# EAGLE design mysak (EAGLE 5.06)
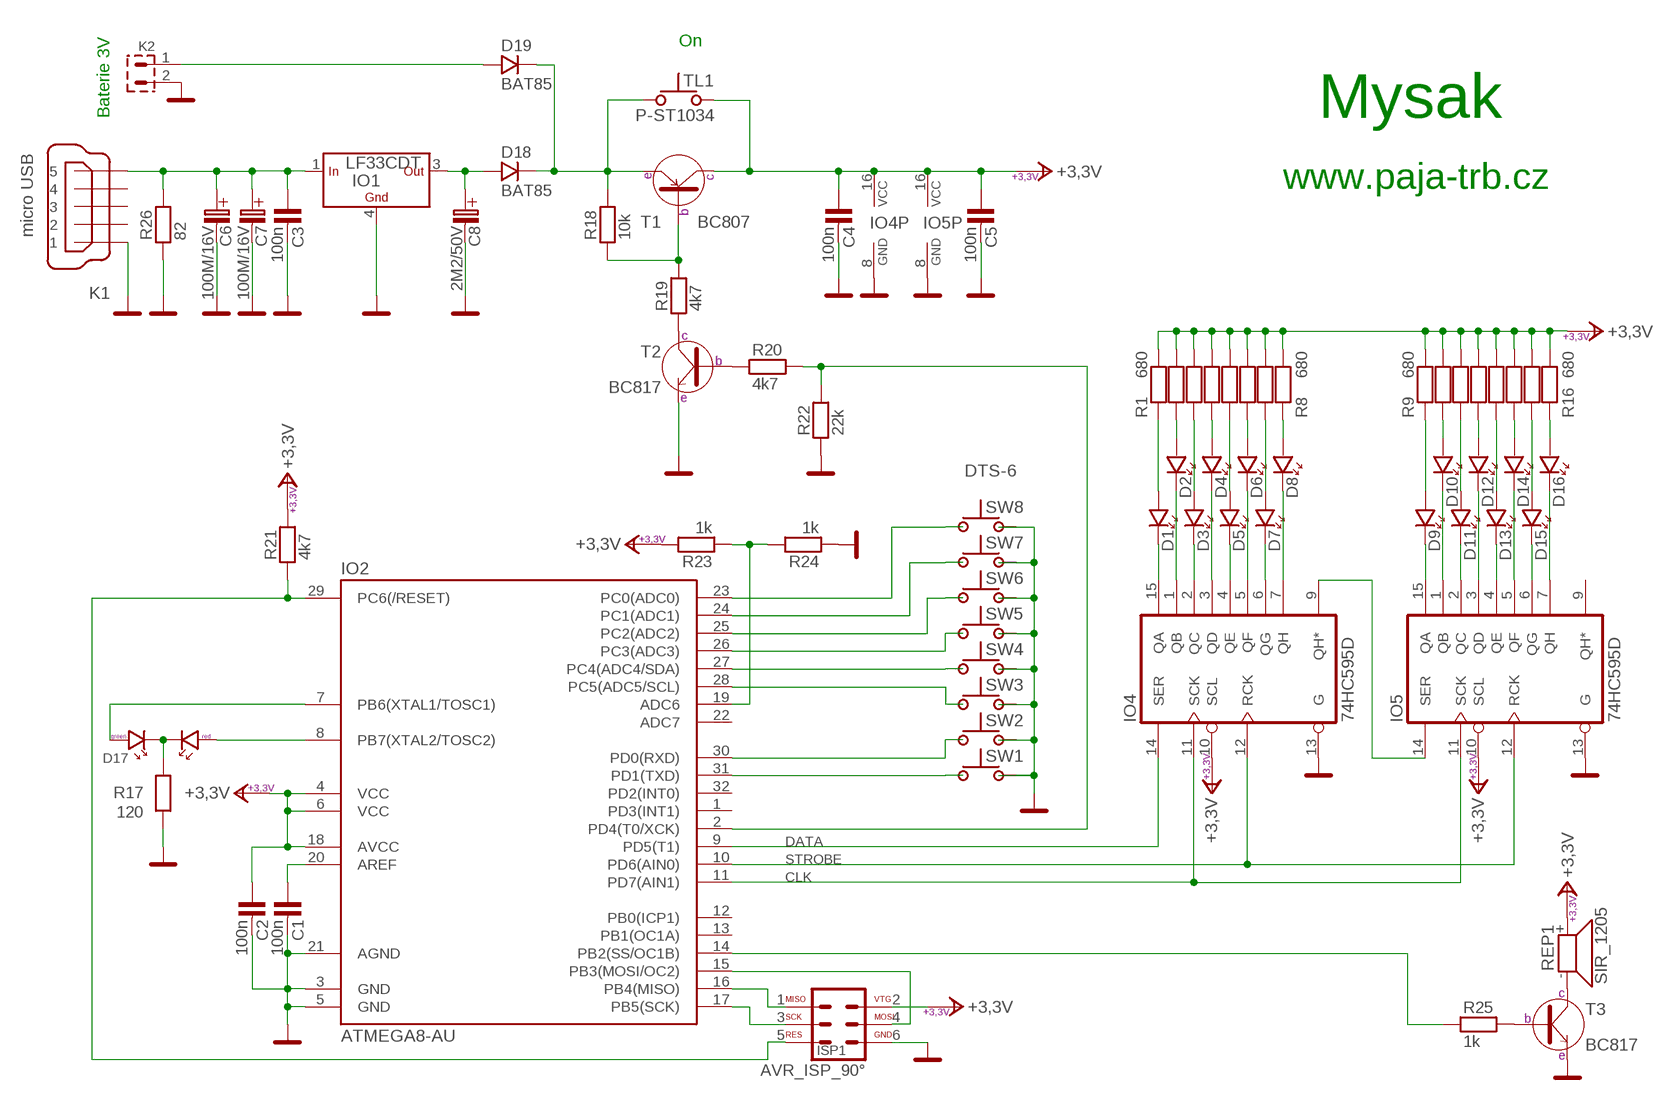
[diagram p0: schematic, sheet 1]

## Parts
C1  100n  C-KER_0805  [0805]
C2  100n  C-KER_0805  [0805]
C3  100n  C-KER_1206  [1206]
C4  100n  C-KER_1206  [1206]
C5  100n  C-KER_1206  [1206]
C6  100M/16V  100M/16V_SMD  [C_EL-SMD_D]
C7  100M/16V  100M/16V_SMD  [C_EL-SMD_D]
C8  2M2/50V  [C_EL_2]
D1  LED_3  [LED_3]
D2  LED_3  [LED_3]
D3  LED_3  [LED_3]
D4  LED_3  [LED_3]
D5  LED_3  [LED_3]
D6  LED_3  [LED_3]
D7  LED_3  [LED_3]
D8  LED_3  [LED_3]
D9  LED_3  [LED_3]
D10  LED_3  [LED_3]
D11  LED_3  [LED_3]
D12  LED_3  [LED_3]
D13  LED_3  [LED_3]
D14  LED_3  [LED_3]
D15  LED_3  [LED_3]
D16  LED_3  [LED_3]
D17  LED_DUO_5  [LED_5-DUO]
D18  BAT85  D_7,5  [DO35]
D19  BAT85  D_7,5  [DO35]
IO1  LF33CDT  LF_CDT  [DPAK]
IO2  ATMEGA8-AU  [TQFP32-08]
IO4  74HC595D  [SO16]
IO5  74HC595D  [SO16]
ISP1  AVR_ISP_90°  [MLW06A]
K1  micro USB  MINI-USB-UX60A-MB-5ST  [UX60A-MB-5ST]
K2  PSH02-02W  [PSH02-02W]
R1  680  R_0805  [0805]
R2  680  R_0805  [0805]
R3  680  R_0805  [0805]
R4  680  R_0805  [0805]
R5  680  R_0805  [0805]
R6  680  R_0805  [0805]
R7  680  R_0805  [0805]
R8  680  R_0805  [0805]
R9  680  R_0805  [0805]
R10  680  R_0805  [0805]
R11  680  R_0805  [0805]
R12  680  R_0805  [0805]
R13  680  R_0805  [0805]
R14  680  R_0805  [0805]
R15  680  R_0805  [0805]
R16  680  R_0805  [0805]
R17  120  R_0805  [0805]
R18  10k  R_1206  [1206]
R19  4k7  R_1206  [1206]
R20  4k7  R_1206  [1206]
R21  4k7  R_7,5  [R-7,5]
R22  22k  R_1206  [1206]
R23  1k  R_0805  [0805]
R24  1k  R_0805  [0805]
R25  1k  R_1206  [1206]
R26  82  R__2W  [R-_2W]
REP1  SIR_1205  [LD-BZEG-1205]
SW1  DTS-6  [DTS-6]
SW2  DTS-6  [DTS-6]
SW3  DTS-6  [DTS-6]
SW4  DTS-6  [DTS-6]
SW5  DTS-6  [DTS-6]
SW6  DTS-6  [DTS-6]
SW7  DTS-6  [DTS-6]
SW8  DTS-6  [DTS-6]
T1  BC807  [SOT-23]
T2  BC817  [SOT-23]
T3  BC817  [SOT-23]
TL1  P-ST1034  [P-ST1034]

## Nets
+3,3V: C2.1 C4.1 C5.1 IO2.4(VCC) IO2.6(VCC) IO2.18(AVCC) IO4.10(SCL) IO4.16(VCC) IO5.10(SCL) IO5.16(VCC) ISP1.2 R1.2 R2.2 R3.2 R4.2 R5.2 R6.2 R7.2 R8.2 R9.2 R10.2 R11.2 R12.2 R13.2 R14.2 R15.2 R16.2 R21.2 R23.2 REP1.+ T1.3(C) TL1.S
CLK: IO2.11(PD7(AIN1)) IO4.11(SCK) IO5.11(SCK)
D2: D1.A R1.1
D3: D4.K IO4.3(QD)
DATA: IO2.9(PD5(T1)) IO4.14(SER)
DD: D17.K R17.2
GND: C1.2 C2.2 C3.2 C4.2 C5.2 C6.-(C_EL-) C7.-(C_EL-) C8.C-(C_EL-) IO1.4(GND) IO2.3(GND) IO2.5(GND) IO2.21(AGND) IO4.8(GND) IO4.13(G) IO5.8(GND) IO5.13(G) ISP1.6 K1.1 K2.2 R17.1 R22.1 R24.1 R26.1 SW1.3 SW1.4(2A) SW2.3 SW2.4(2A) SW3.3 SW3.4(2A) SW4.3 SW4.4(2A) SW5.3 SW5.4(2A) SW6.3 SW6.4(2A) SW7.3 SW7.4(2A) SW8.3 SW8.4(2A) T2.2(E) T3.2(E)
N$1: D17.A1 IO2.8(PB7(XTAL2/TOSC2))
N$2: IO4.9(QH*) IO5.14(SER)
N$3: C1.1 IO2.20(AREF)
N$4: IO2.23(PC0(ADC0)) SW8.1 SW8.2(1A)
N$5: IO2.29(PC6(/RESET)) ISP1.5 R21.1
N$6: IO2.16(PB4(MISO)) ISP1.1
N$7: IO2.17(PB5(SCK)) ISP1.3
N$8: IO2.15(PB3(MOSI/OC2)) ISP1.4
N$9: IO2.24(PC1(ADC1)) SW7.1 SW7.2(1A)
N$10: IO2.25(PC2(ADC2)) SW6.1 SW6.2(1A)
N$11: IO2.26(PC3(ADC3)) SW5.1 SW5.2(1A)
N$12: IO2.27(PC4(ADC4/SDA)) SW4.1 SW4.2(1A)
N$13: IO2.28(PC5(ADC5/SCL)) SW3.1 SW3.2(1A)
N$14: IO2.30(PD0(RXD)) SW2.1 SW2.2(1A)
N$15: IO2.31(PD1(TXD)) SW1.1 SW1.2(1A)
N$16: IO2.19(ADC6) R23.1 R24.2
N$17: C8.C+(C_EL+) D18.A IO1.3(OUT)
N$18: D17.A2 IO2.7(PB6(XTAL1/TOSC1))
N$20: R19.1 T2.3(C)
N$21: R20.1 T2.1(B)
N$22: D18.K D19.K R18.2 T1.2(E) TL1.1
N$23: R18.1 R19.2 T1.1(B)
N$24: IO2.2(PD4(T0/XCK)) R20.2 R22.2
N$26: IO2.14(PB2(SS/OC1B)) R25.1
N$35: REP1.- T3.3(C)
N$36: D2.A R2.1
N$37: D4.A R4.1
N$39: D6.A R6.1
N$40: D8.A R8.1
N$41: D10.A R10.1
N$42: D12.A R12.1
N$43: D14.A R14.1
N$44: D16.A R16.1
N$46: D3.A R3.1
N$47: D5.A R5.1
N$48: D7.A R7.1
N$49: D8.K IO4.7(QH)
N$50: D6.K IO4.5(QF)
N$51: D7.K IO4.6(QG)
N$52: D5.K IO4.4(QE)
N$54: D3.K IO4.2(QC)
N$55: D2.K IO4.1(QB)
N$56: D1.K IO4.15(QA)
N$57: D9.A R9.1
N$58: D9.K IO5.15(QA)
N$59: D10.K IO5.1(QB)
N$60: D12.K IO5.3(QD)
N$61: D11.K IO5.2(QC)
N$62: D11.A R11.1
N$63: D13.A R13.1
N$64: D13.K IO5.4(QE)
N$65: D14.K IO5.5(QF)
N$66: D15.A R15.1
N$67: D15.K IO5.6(QG)
N$68: D16.K IO5.7(QH)
N$69: C3.1 C6.+(C_EL+) C7.+(C_EL+) IO1.1(IN) K1.5 R26.2
N$70: D19.A K2.1
N$71: R25.2 T3.1(B)
STROBE: IO2.10(PD6(AIN0)) IO4.12(RCK) IO5.12(RCK)
Unconnected: IO2.1(PD3(INT1)) IO2.12(PB0(ICP1)) IO2.13(PB1(OC1A)) IO2.22(ADC7) IO2.32(PD2(INT0)) IO5.9(QH*) K1.2 K1.3 K1.4

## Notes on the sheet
- On
- Baterie 3V | Mysak
- www.paja-trb.cz

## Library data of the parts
C1-C5 = #PaJa_32:C-KER: Kondenzator - keramicky
C6 C7 = #PaJa_C-el_2:100M/16V
C8 = #PaJa_C-el_2:2M2/50V
D1-D16 = #PaJa_32:LED: LED - jednobarevna
D17 = #PaJa_32:LED_DUO: LED dioda - dvoubarevna - 3 vyvody, spol. Katoda
D18 D19 = #PaJa_32:D: Dioda - univerzální
IO1 = #PaJa_32:LF_C: LF??C - stabilizatory low-drop Out= 1,5 / 1,8 / 2,5 / 3,3 / 4,7 / 5 / 6 / 8 / 5,5 / 9 / 12 V Avaiable in +- 1% (AB) , +- 2% (C)
IO2 = atmega8:ATMEGA8
IO4 IO5 = 74xx-eu:74*595: 8-bit SHIFT REGISTER, output latch
ISP1 = #PaJa_32:AVR_ISP: AVR ISP konektor (dle standardu)
K1 = con-hirose:MINI-USB-: Hirose MINI USB Connector UX60-MB-5S8: Through-hole / SMT Supplier: UX60-MB-5ST: Through-hole / SMT Supplier: UX60A-MB-5ST: Through-hole / SMT Supplier: Source: http://www.hirose.co.jp/cataloge_hp/e24000019.pdf
K2 = #PaJa_konektory:PSH02-02: Konektory se zamkem - vidlice - 2pin
R1-R26 = #PaJa_32:R: Rezistor
REP1 = #PaJa_32:SIR: Piezo-sirenka - 70dB - 3V az 16V
SW1-SW8 = #PaJa_prepinace:DTS?6: &micro;-tlacitko
T1 = #PaJa_32:BC807: SMD tranzistor - PNP - ekv. BC327
T2 T3 = #PaJa_32:BC817: SMD tranzistor - NPN - ekv. BC337
TL1 = #PaJa_prepinace:P-ST1034: &micro;-spinac - (10x10mm)

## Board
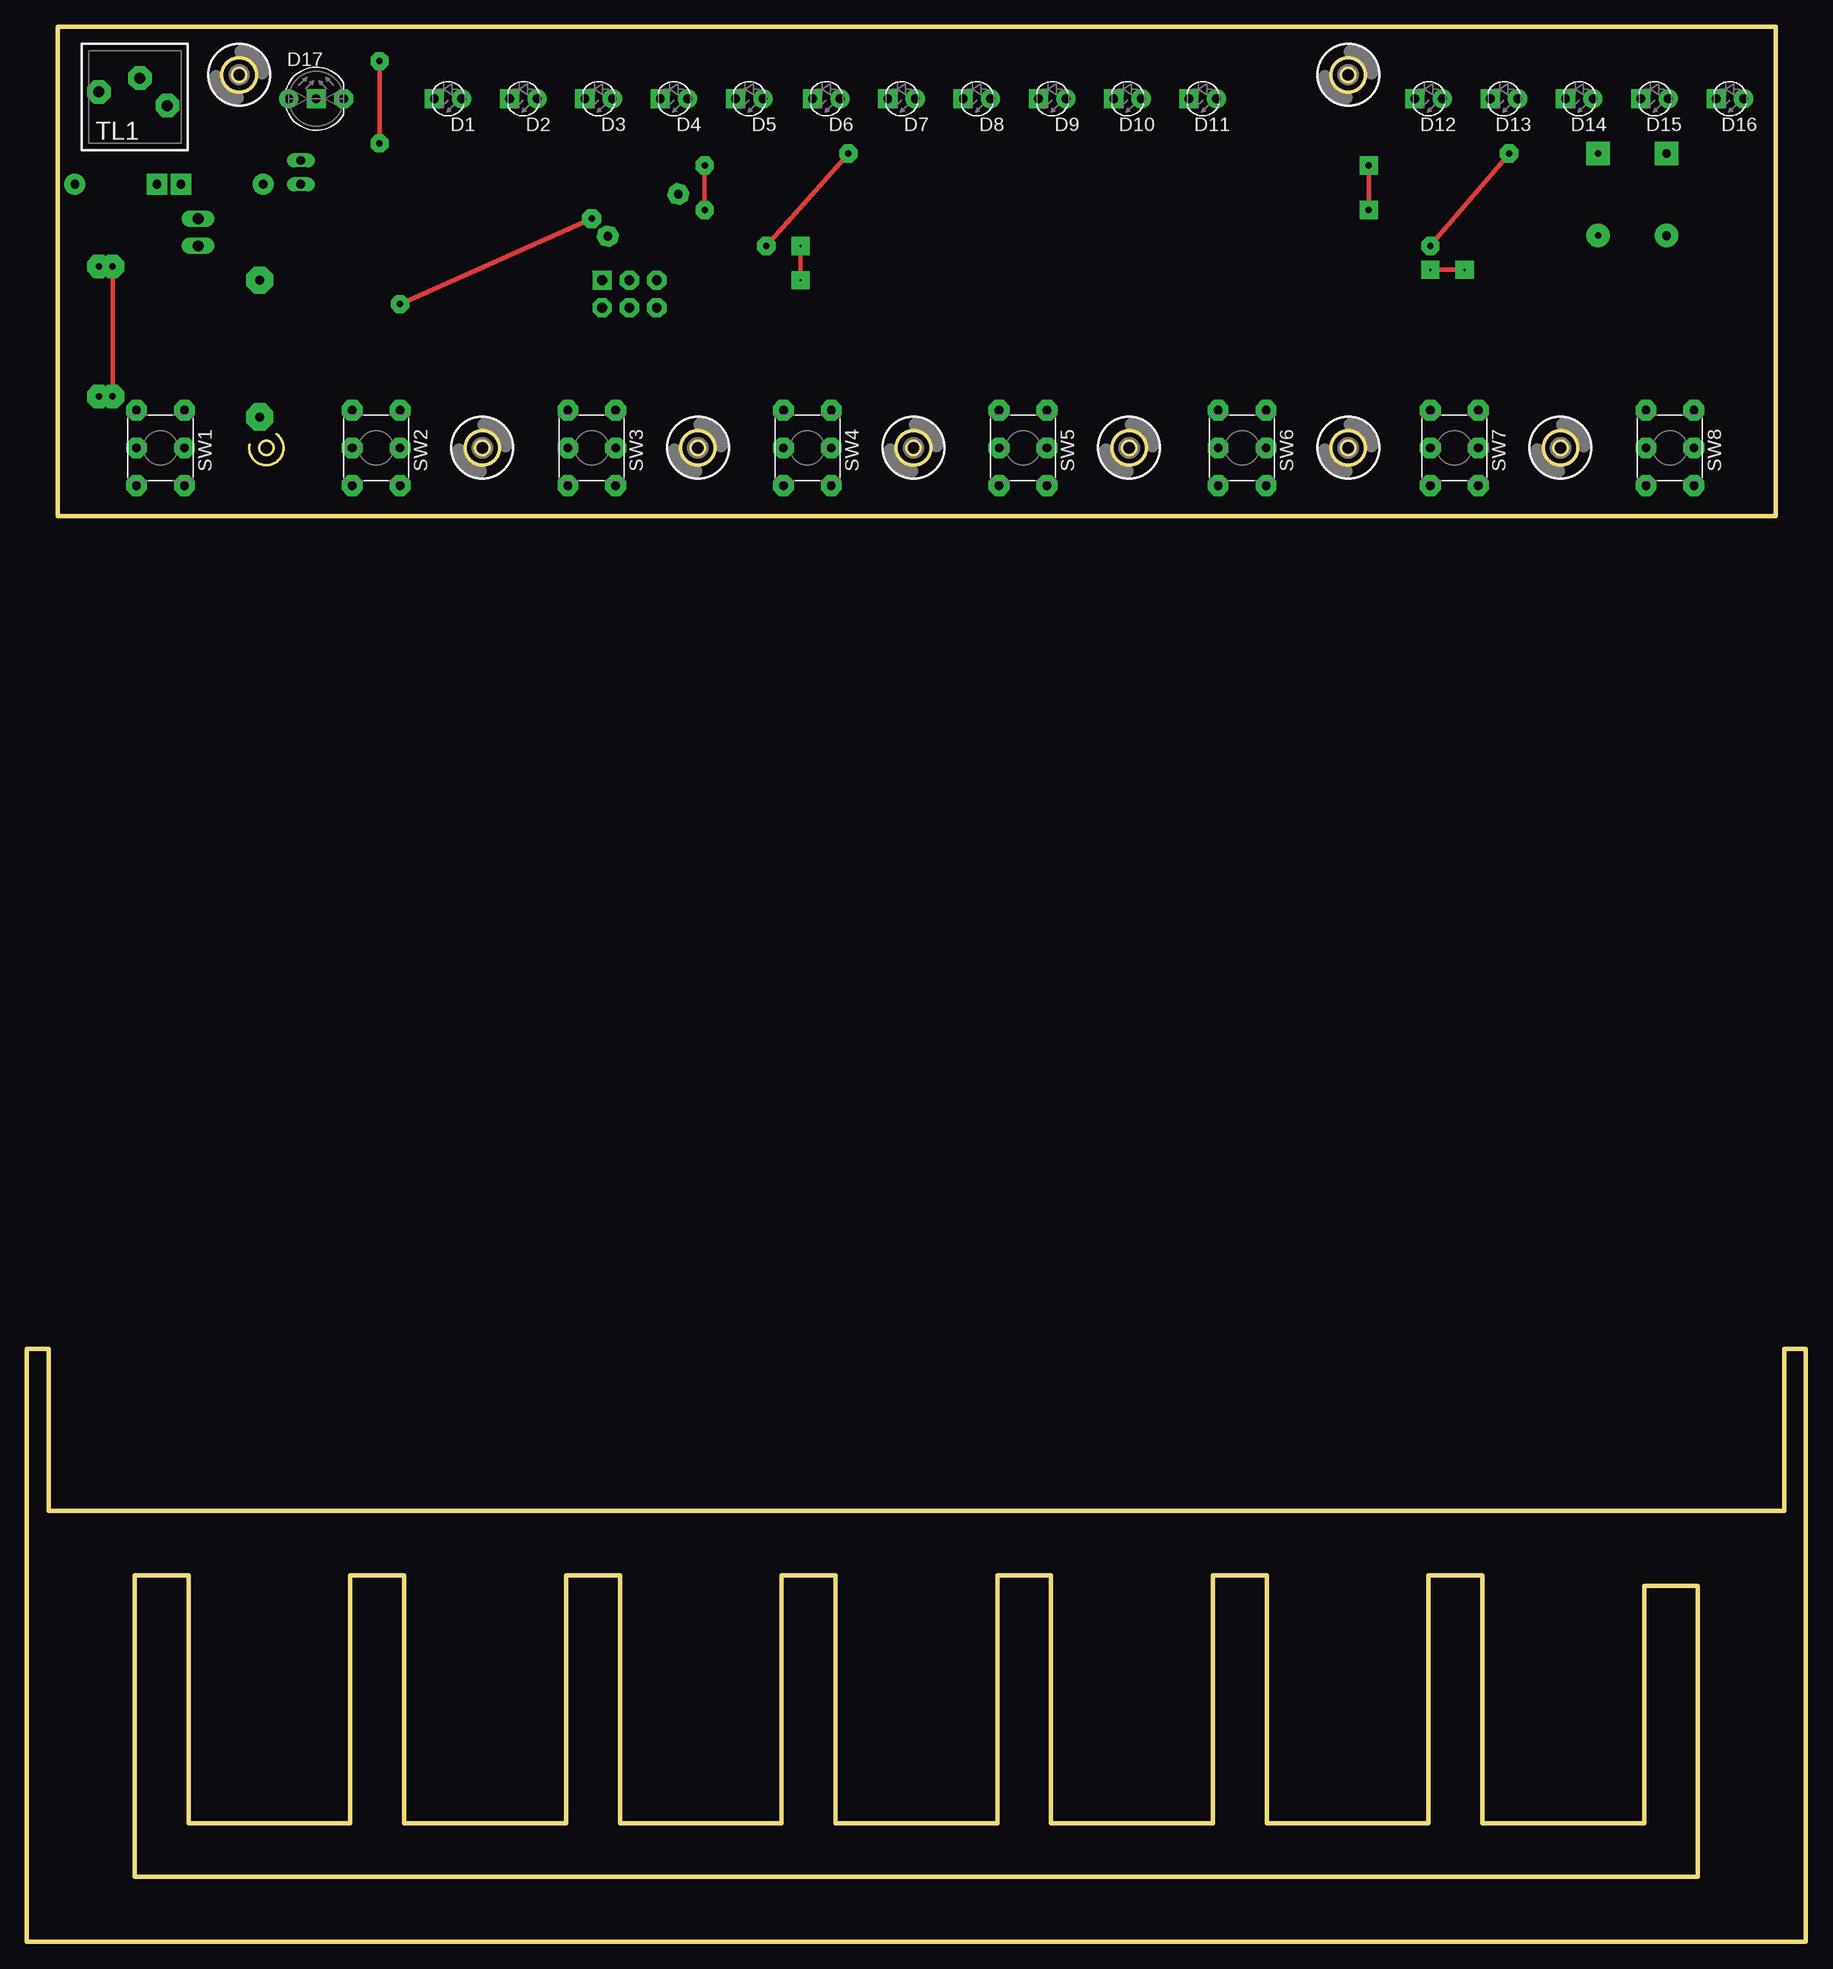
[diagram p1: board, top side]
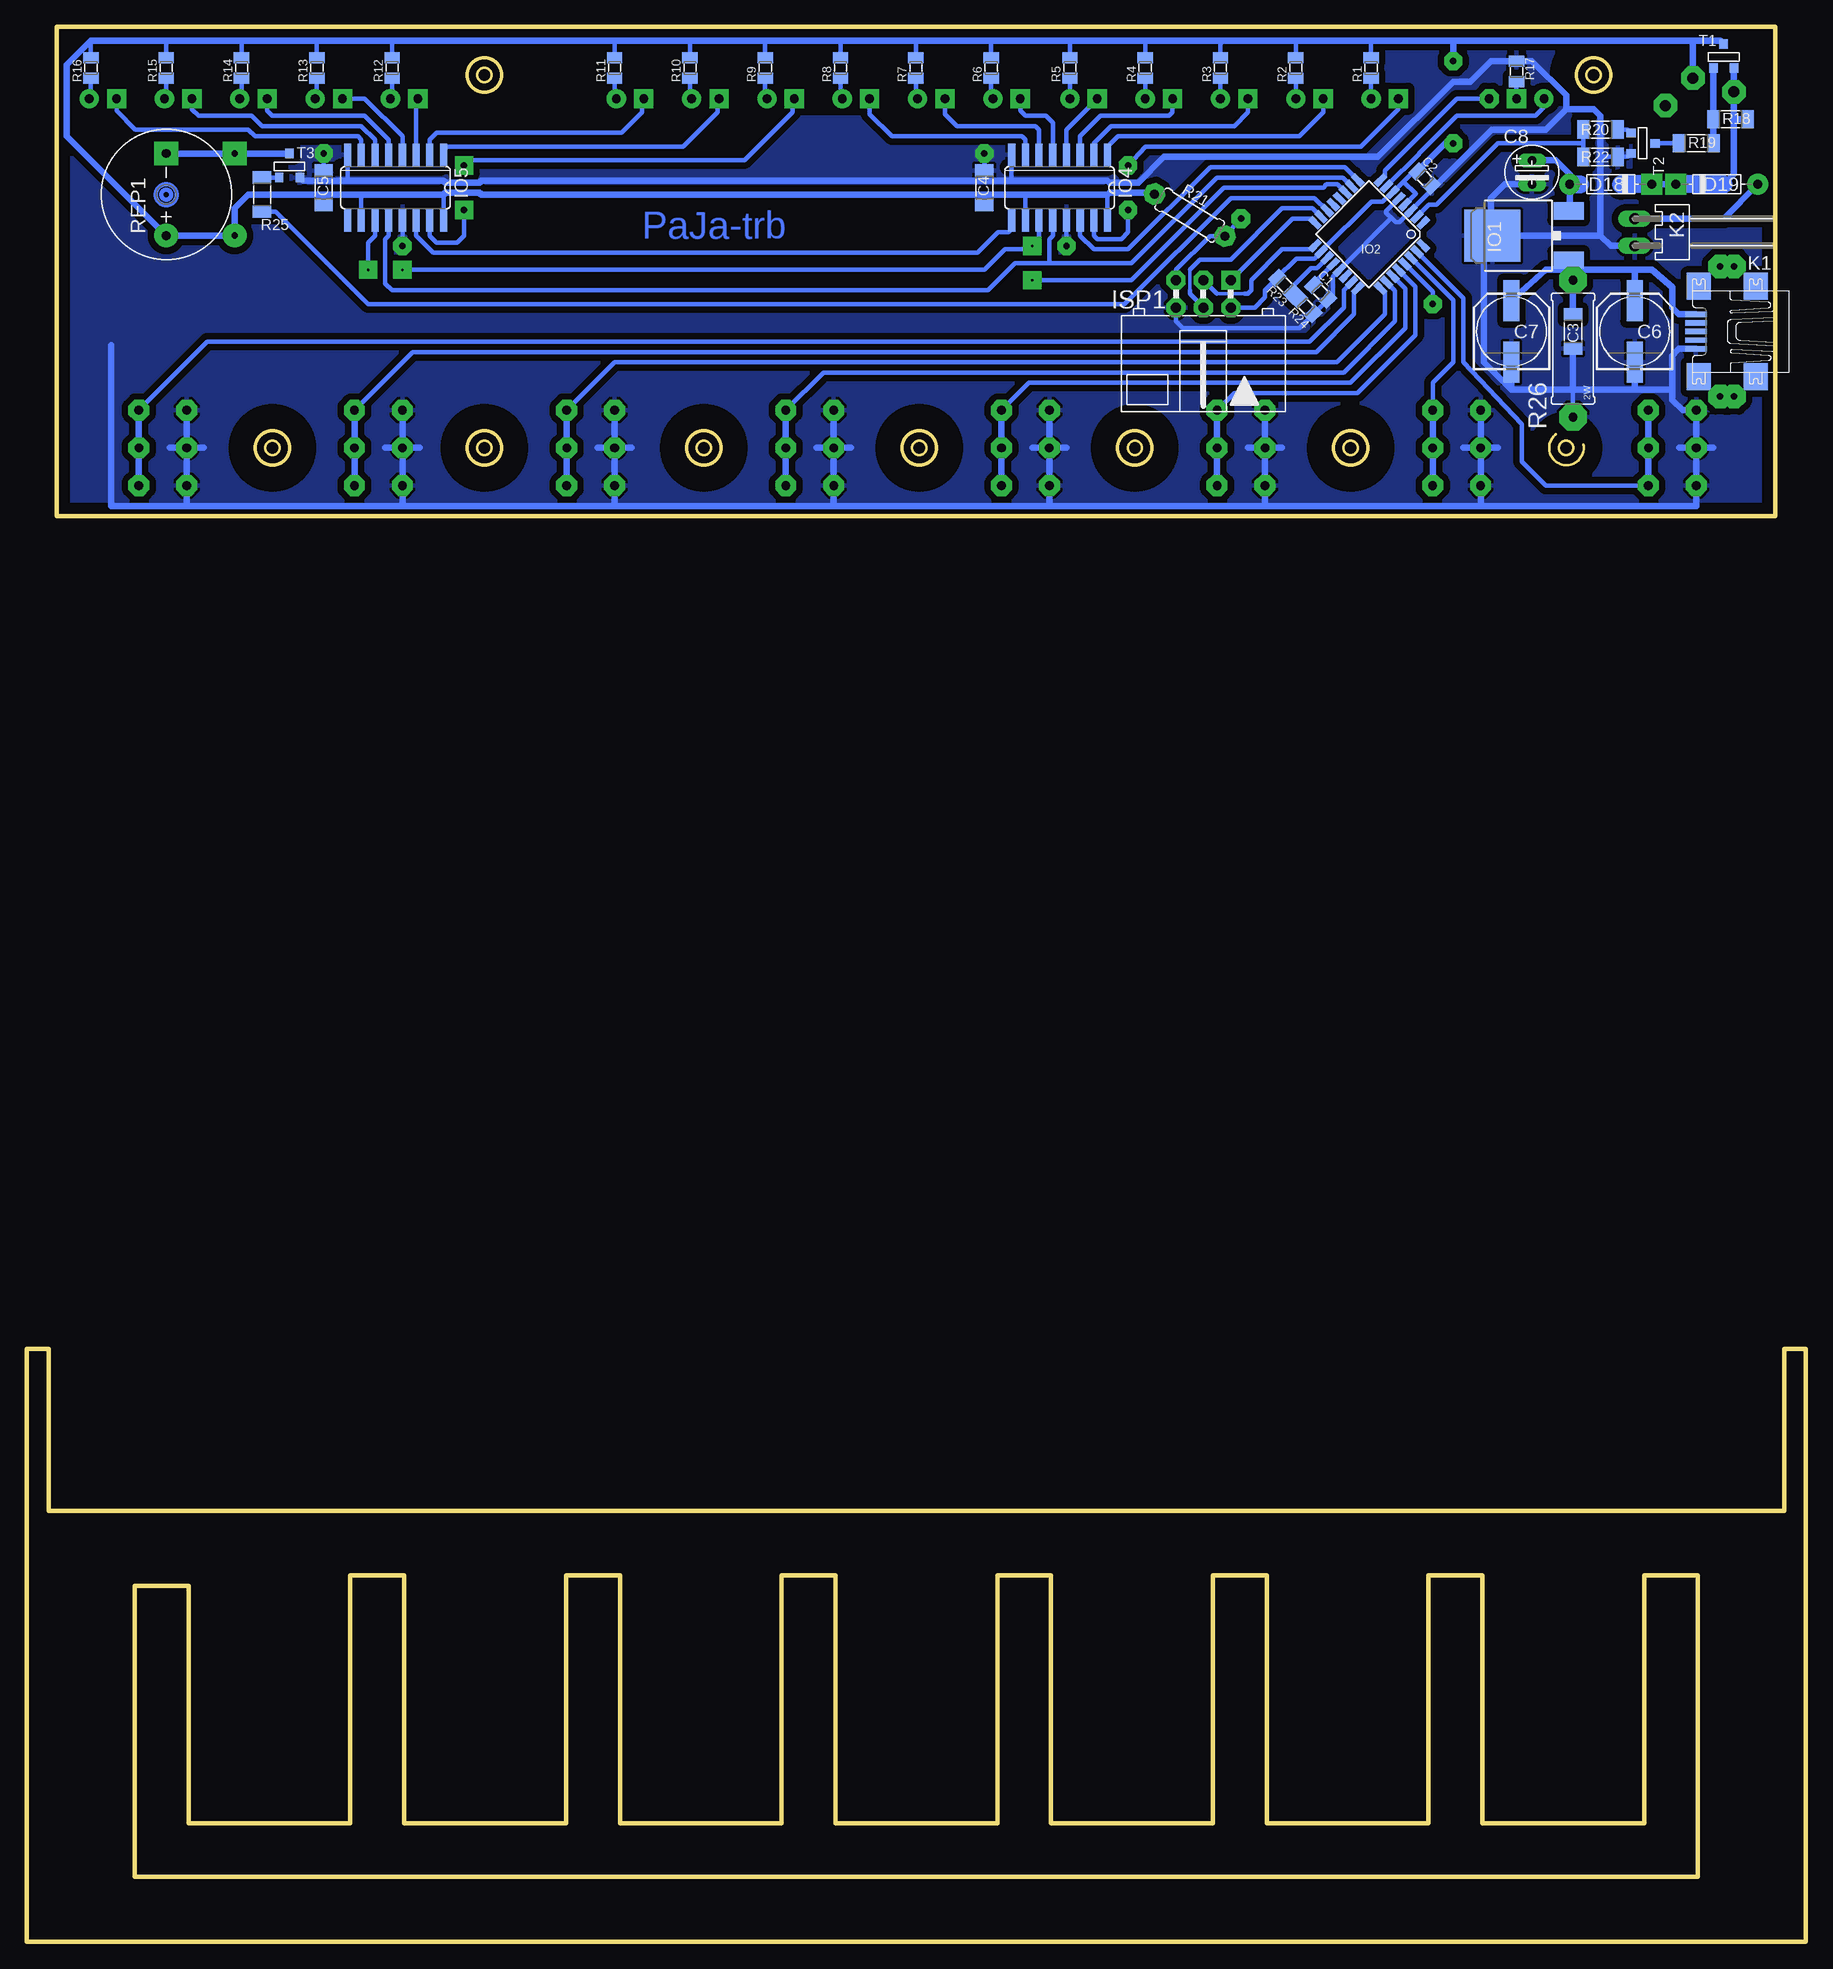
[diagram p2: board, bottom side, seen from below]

Size 165 x 177.6 mm. Coordinates in mm from the lower left corner, seen from the top.
Outline: 0,40 0,39.97
Outline: 0,39.97 0,0 165,0 165,39.97
Outline: 165,40 165,39.97
Outline: 0,39.97 0,54.97 2,54.97 2,39.97 163,39.97 163,54.97 165,54.97 165,39.97
Outline: 23.18,139.83 arc-244 20.64,138.88
Outline: 2.86,132.21 162.23,132.21 162.23,177.6 2.86,177.6 2.86,132.21
Outline: 10,34 15,34 15,11 30,11 30,34 35,34 35,11 50,11 50,34 55,34 55,11 70,11 70,34 75,34 75,11 90,11 90,34 95,34 95,11 110,11 110,34 115,34 115,11 130,11 130,34 135,34 135,11 150,11 150,33 155,33 155,6 10,6 10,34
Outline: circle at 22.23,138.56 radius 0.64
Copper layers (1*16): Top 0.035mm / dielectric 1.5mm / Bottom 0.035mm
Design rules "default": minimum track width 10mil, minimum drill 24mil, track to track 8mil, track to pad 8mil, pad to pad 8mil, via to via 8mil, smd to smd 8mil, copper to edge 40mil, drill to drill 8mil, minimum pad ring 10mil, minimum via ring 8mil, stop-mask expansion 4mil, vias tented up to drill 0mil, thermal gap 10mil
bRestrict: area 9.7,138.1 to 10.6,139; area 29.7,138.1 to 30.6,139; area 49.7,138.1 to 50.6,139; area 69.7,138.1 to 70.6,139; area 89.7,138.1 to 90.6,139; area 110,138.1 to 110.9,139; area 129.7,138.1 to 130.6,139; area 149.7,138.1 to 150.6,139; area 19.7,136 to 24.8,141.1; 8 lines

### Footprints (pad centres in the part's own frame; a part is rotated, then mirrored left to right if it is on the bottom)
0805 = smd 1.016 x 1.422: 1 -0.953,0; 2 0.953,0
1206 = smd 1.143 x 1.702: 1 -1.587,0; 2 1.587,0
C_EL-SMD_D = smd 3.81 x 1.473: + 2.857,0; - -2.857,0
C_EL_2 = drill 0.813 pad 1.27 long: C+ 0,0; C- 2.223,0
LED_3 = drill 0.813 pad 1.778 round: A -1.27,0 | drill 0.813 pad 1.778 square: K 1.27,0
LED_5-DUO = drill 0.813 pad 1.778 octagon: A1 2.54,0 | drill 0.813 pad 1.778 round: A2 -2.54,0 | drill 0.813 pad 1.778 square: K 0,0
DO35 = drill 0.813 pad 1.93 round: A -3.81,0 | drill 0.813 pad 1.93 square: K 3.81,0
DPAK = smd 1.6 x 2.8: 1 -2.28,-4.992; 3 2.28,-4.992 | smd 4.826 x 5.191: 4 0,2.096
TQFP32-08 = smd 1.27 x 0.559: 1 -4.293,2.8; 2 -4.293,2; 3 -4.293,1.2; 4 -4.293,0.4; 5 -4.293,-0.4; 6 -4.293,-1.2; 7 -4.293,-2; 8 -4.293,-2.8; 17 4.293,-2.8; 18 4.293,-2; 19 4.293,-1.2; 20 4.293,-0.4; 21 4.293,0.4; 22 4.293,1.2; 23 4.293,2; 24 4.293,2.8 | smd 0.559 x 1.27: 9 -2.8,-4.293; 10 -2,-4.293; 11 -1.2,-4.293; 12 -0.4,-4.293; 13 0.4,-4.293; 14 1.2,-4.293; 15 2,-4.293; 16 2.8,-4.293; 25 2.8,4.293; 26 2,4.293; 27 1.2,4.293; 28 0.4,4.293; 29 -0.4,4.293; 30 -1.2,4.293; 31 -2,4.293; 32 -2.8,4.293
SO16 = smd 0.66 x 2.032: 1 -4.445,-3.073; 2 -3.175,-3.073; 3 -1.905,-3.073; 4 -0.635,-3.073; 5 0.635,-3.073; 6 1.905,-3.073; 7 3.175,-3.073; 8 4.445,-3.073; 9 4.445,3.073; 10 3.175,3.073; 11 1.905,3.073; 12 0.635,3.073; 13 -0.635,3.073; 14 -1.905,3.073; 15 -3.175,3.073; 16 -4.445,3.073
MLW06A = drill 0.914 pad 1.778 square: 1 -2.54,-1.27 | drill 0.914 pad 1.778 octagon: 2 -2.54,1.27; 3 0,-1.27; 4 0,1.27; 5 2.54,-1.27; 6 2.54,1.27
UX60A-MB-5ST = smd 2 x 0.5: 1 2.25,1.6; 2 2.25,0.8; 3 2.25,0; 4 2.25,-0.8; 5 2.25,-1.6 | smd 2.2 x 2.5: M1 -3.3,-4.2; M2 -3.3,4.2; M3 2,4.2; M4 2,-4.2
PSH02-02W = drill 1.016 pad 1.422 long: 1 -1.27,0; 2 1.27,0
R-7,5 = drill 0.813 pad 1.93 octagon: 1 -3.81,0; 2 3.81,0
R-_2W = drill 0.813 pad 2.54 octagon: 1 -6.35,0; 2 6.35,0
LD-BZEG-1205 = drill 0.813 pad 2.184 round: + -3.81,0 | drill 0.813 pad 2.184 square: - 3.81,0
DTS-6 = drill 0.813 pad 1.93 octagon: 1 -3.493,2.223; 2 3.493,2.223; 3 -3.493,-2.223; 4 3.493,-2.223
SOT-23 = smd 0.787 x 0.889: 1 -0.953,-0.953; 2 0.953,-0.953; 3 0,1.27
P-ST1034 = drill 1.016 pad 2.184 octagon: 1 -3.175,0.635; 2 3.175,-0.635; S 0.635,1.905
HOLE_3,0 = hole 3.2: 0,0

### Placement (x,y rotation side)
C1  45,152.99 315 bottom
C2  35.34,163.54 315 bottom
C3  21.59,149.35 270 bottom
C4  76.2,162.69 90 bottom
C5  137.48,162.69 90 bottom
C6  15.88,149.35 90 bottom
C7  27.3,149.35 90 bottom
C8  25.4,165.23 270 bottom
D1  39.05,170.94 180 top
D2  46.04,170.94 180 top
D3  53.02,170.94 180 top
D4  60.01,170.94 180 top
D5  66.99,170.94 180 top
D6  74.14,170.94 180 top
D7  81.12,170.94 180 top
D8  88.11,170.94 180 top
D9  95.09,170.94 180 top
D10  102.08,170.94 180 top
D11  109.06,170.94 180 top
D12  130.02,170.94 180 top
D13  137,170.94 180 top
D14  143.99,170.94 180 top
D15  150.97,170.94 180 top
D16  157.96,170.94 180 top
D17  26.83,170.94 0 top
D18  18.1,163 0 bottom
D19  8.26,163 180 bottom
IO1  26.99,158.24 90 bottom
IO2  40.51,158.37 225 bottom
IO4  69.22,162.69 180 bottom
IO5  130.81,162.69 180 bottom
ISP1  55.88,152.84 180 bottom
K1  7.94,149.35 180 bottom
K2  15.88,158.56 270 bottom
R1  40.32,173.8 90 bottom
R2  47.31,173.8 90 bottom
R3  54.29,173.8 90 bottom
R4  61.28,173.8 90 bottom
R5  68.26,173.8 90 bottom
R6  75.56,173.8 90 bottom
R7  82.55,173.8 90 bottom
R8  89.53,173.8 90 bottom
R9  96.52,173.8 90 bottom
R10  103.5,173.8 90 bottom
R11  110.49,173.8 90 bottom
R12  131.13,173.8 90 bottom
R13  138.11,173.8 90 bottom
R14  145.1,173.8 90 bottom
R15  152.08,173.8 90 bottom
R16  159.07,173.8 90 bottom
R17  26.83,173.48 270 bottom
R18  6.99,169.04 0 bottom
R19  10.16,166.81 0 bottom
R20  19.05,168.09 180 bottom
R21  57.15,160.15 149.2 bottom
R22  19.05,165.55 180 bottom
R23  48.37,153.66 135 bottom
R24  46.35,151.64 135 bottom
R25  143.19,162.05 90 bottom
R26  21.59,147.76 90 bottom
REP1  152.08,162.05 90 bottom
SW1  12.38,138.56 270 top
SW2  32.38,138.56 270 top
SW3  52.39,138.56 270 top
SW4  72.39,138.56 270 top
SW5  92.39,138.56 270 top
SW6  112.71,138.56 270 top
SW7  132.4,138.56 270 top
SW8  152.4,138.56 270 top
T1  7.62,174.75 0 bottom
T2  15.24,166.81 270 bottom
T3  140.65,164.59 0 bottom
TL1  9.84,170.94 0 top
U$2  [HOLE_3,0]  122.56,173.17 0 top
U$3  [HOLE_3,0]  19.68,173.17 0 top
U$5  [HOLE_3,0]  42.23,138.56 0 top
U$6  [HOLE_3,0]  62.23,138.56 0 top
U$7  [HOLE_3,0]  82.23,138.56 0 top
U$8  [HOLE_3,0]  102.23,138.56 0 top
U$9  [HOLE_3,0]  122.56,138.56 0 top
U$10  [HOLE_3,0]  142.24,138.56 0 top

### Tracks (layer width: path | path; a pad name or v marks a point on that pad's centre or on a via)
+3,3V  (via drill 0.6 pad 1.68, 0.6 pad 2.18)
  Top 0.406: v32.7,174.44 v32.7,166.81
  Bottom 0.406: 126.36,162.05 IO5.16 | 133.99,162.05 IO5.10 | 64.77,162.05 IO4.16 | 72.39,162.05 IO4.10 | 76.2,162.05 C4.1 | 37.32,163.26 IO2.6 39.28,161.4 40.31,161.4 IO2.18 45.58,156.13 47.24,156.13 R23.2 49.04,154.29 50.16,153.16 50.16,152.53 51.12,151.57 ISP1.2 | IO2.4 36.18,162.13 37.32,163.26 | C2.1 36.19,164.39 37.32,163.26 | 60.47,162.05 R21.2 | 137.48,162.05 C5.1 | 40.32,176.34 R1.2 | 47.31,176.34 R2.2 | R3.2 54.29,176.02 53.98,176.34 | 61.28,176.34 R4.2 | R5.2 68.26,176.34 67.94,176.34 | 75.56,176.34 R6.2 | 82.55,176.34 R7.2 | R8.2 89.53,176.34 89.85,176.34 | 96.52,176.34 R9.2 | 103.5,176.34 R10.2 | 110.49,176.34 R11.2 | R12.2 131.13,176.34 131.44,176.34 | 138.11,176.34 R13.2 | 145.1,176.34 R14.2 | 152.08,176.34 R15.2 | 159.07,176.34 R16.2
  Bottom 0.61: C2.1 33.41,166.81 v32.7,166.81 | 32.7,176.34 v32.7,174.44 | 32.7,176.34 40.32,176.34 47.31,176.34 53.98,176.34 61.28,176.34 67.94,176.34 75.56,176.34 82.55,176.34 89.85,176.34 96.52,176.34 103.5,176.34 110.49,176.34 131.44,176.34 138.11,176.34 145.1,176.34 152.08,176.34 159.07,176.34 161.29,174.12 161.29,167.45 REP1.+ v145.73,158.24 145.73,160.78 144.46,162.05 137.48,162.05 133.99,162.05 126.36,162.05 126.21,162.21 123.03,162.21 122.87,162.05 76.2,162.05 72.39,162.05 64.77,162.05 64.61,162.21 60.96,162.21 60.48,162.05 60.47,162.05 | 10.48,176.34 7.94,176.34 T1.3 | 10.48,176.34 32.7,176.34 | TL1.S 10.48,176.34
CLK  (via drill 0.2 pad 1.68)
  Top 0.406: v130.18,155.07 v133.35,155.07 | v71.75,154.12 v71.75,157.29
  Bottom 0.406: 71.12,156.97 IO4.11 | 71.44,156.97 71.12,156.97 | 71.44,156.97 74.3,156.97 76.2,155.07 v130.18,155.07 | IO5.11 132.72,158.24 133.35,157.61 v133.35,155.07 | 71.44,156.97 v71.75,157.29 71.44,157.29 71.12,156.97 | v71.75,154.12 62.55,154.12 53.98,162.69 44.77,162.69 44.45,163 43.44,163 IO2.11
D2
  Bottom 0.406: R1.1 D1.A
D3
  Bottom 0.406: IO4.3 67.31,167.45 65.41,169.36 59.05,169.36 58.74,169.67 D4.K
DATA
  Bottom 0.406: IO4.14 67.31,158.24 66.04,156.97 62.87,156.97 55.24,164.59 42.77,164.59 IO2.9
DD
  Bottom 0.406: R17.2 D17.K | R17.2
GND  (via drill 0.6 pad 1.68, 0.8 pad 1.93)
  Top 0.406: v76.2,165.86 v68.58,157.29 | v137.48,165.86 v130.18,157.29
  Bottom 0.406: SW7.3 v130.18,138.56 SW7.4 | 73.66,163.32 IO4.8 | 135.25,163.32 IO5.8 | 76.2,163.32 C4.2 v76.2,165.86 | v68.58,157.29 IO4.13 | v130.18,157.29 IO5.13 | v137.48,165.86 C5.2 137.48,163.32 | IO2.5 38.94,160.51 38.94,160.4 38.26,159.72 | 38.26,159.72 38.04,159.5 37.69,159.5 IO2.3 34.5,162.69 C2.2 | 38.26,159.72 38.43,159.89 IO2.21 43.88,154.44 43.88,152.76 C1.2 R24.1 46.97,149.67 57.78,149.67 58.42,150.31 ISP1.6 | 19.05,165.55 R22.1 16.51,165.55 T2.2 | 29.21,158.24 IO1.4 29.21,158.37 | C2.2 | 26.67,174.44 26.83,174.28 | 21.59,143.96 R26.1
  Bottom 0.61: v10.16,138.56 SW1.4 10.16,133.16 30.16,133.16 | v10.16,138.56 SW1.3 11.43,142.05 12.38,143 12.38,143.96 | 30.16,133.16 SW2.4 v30.16,138.56 | 30.16,133.16 50.16,133.16 | 50.16,133.16 70.17,133.16 | 70.17,133.16 90.17,133.16 | 90.17,133.16 110.49,133.16 | 110.49,133.16 130.18,133.16 | 130.18,133.16 150.18,133.16 | 150.18,133.16 SW8.4 v150.18,138.56 | v150.18,138.56 SW8.3 | v110.49,138.56 SW6.4 110.49,133.16 | v110.49,138.56 SW6.3 | 130.18,133.16 v130.18,138.56 | v130.18,138.56 SW7.3 | v90.17,138.56 SW5.4 90.17,133.16 | v90.17,138.56 SW5.3 | v70.17,138.56 SW4.4 70.17,133.16 | v70.17,138.56 SW4.3 | v50.16,138.56 SW3.4 50.16,133.16 | v50.16,138.56 SW3.3 | v30.16,138.56 SW2.3 | T3.2 139.38,163.32 137.48,163.32 135.25,163.32 126.36,163.32 126.21,163.16 123.03,163.16 122.87,163.32 76.2,163.32 73.66,163.32 64.77,163.32 64.61,163.16 61.91,163.16 59.53,165.55 39.69,165.55 32.7,172.53 31.11,172.53 29.21,174.44 26.67,174.44 25.4,174.44 22.23,171.26 22.23,169.99 | 19.05,158.24 19.05,165.55 19.05,169.36 19.68,169.99 22.23,169.99 | 19.05,158.24 18.1,157.29 K2.2 | IO1.4 19.05,158.24 | 12.38,143.96 15.88,143.96 | 15.88,143.96 C6.- | 27.3,143.96 C7.- | C8.C- 27.94,163 29.21,161.74 29.21,158.37 | 34.5,162.69 29.1,168.09 24.13,168.09 22.23,169.99 | 26.83,174.28 R17.1 | 150.18,133.16 157.16,133.16 157.16,148.08 | 29.21,158.24 29.84,158.24 29.84,146.5 27.3,143.96 | K1.1 11.76,147.75 12.38,147.13 12.38,143.96 | v10.16,138.56 11.75,138.56 | v10.16,138.56 8.57,138.56 | v110.49,138.56 112.08,138.56 | v110.49,138.56 108.9,138.56 | v130.18,138.56 131.76,138.56 | v130.18,138.56 128.59,138.56 | v150.18,138.56 151.76,138.56 | v150.18,138.56 148.59,138.56
  Bottom 0.61: v90.17,138.56 91.76,138.56 | v90.17,138.56 88.58,138.56 | v70.17,138.56 71.75,138.56 | v70.17,138.56 68.58,138.56 | v50.16,138.56 51.75,138.56 | v50.16,138.56 48.58,138.56 | v30.16,138.56 31.75,138.56 | v30.16,138.56 28.57,138.56 | 15.88,143.96 21.59,143.96 | 21.59,143.96 27.3,143.96 | 21.59,143.96 C3.2
  pour Bottom (isolate 0.61): 2.86,132.21 2.86,177.61 162.24,177.61 162.24,132.21
N$1
  Bottom 0.406: D17.A1 32.38,170.94 39.05,164.28 39.05,163.79 IO2.8
N$2
  Bottom 0.406: IO4.9 73.66,158.88 73.98,158.56 74.93,158.56 76.83,156.66 127.32,156.66 128.91,158.24 IO5.14
N$3
  Bottom 0.406: IO2.20 45.67,153.78 C1.1
N$4  (via drill 0.8 pad 1.93)
  Bottom 0.406: IO2.23 42.86,153.19 42.86,151.57 46.04,148.4 148.27,148.4 SW8.1
  Bottom 0.61: SW8.1 v154.62,138.56 SW8.2
N$5  (via drill 0.6 pad 1.68, 0.6 pad 1.78)
  Top 0.406: v34.61,151.89 v52.39,159.83
  Bottom 0.406: IO2.29 34.61,153.04 v34.61,151.89 | ISP1.5 58.42,155.07 55.29,158.2 R21.1 v52.39,159.83
N$6
  Bottom 0.406: IO2.16 45.92,159.83 47.62,159.83 ISP1.1
N$7
  Bottom 0.305: 52.07,152.84 54.61,152.84
  Bottom 0.406: IO2.17 45.87,156.97 48.58,156.97 51.44,154.12 51.44,153.16 51.75,152.84 52.07,152.84 | 54.61,152.84 ISP1.3
N$8
  Bottom 0.305: 57.15,155.07 57.15,153.16
  Bottom 0.406: IO2.15 45.74,160.78 48.58,160.78 53.34,156.02 56.2,156.02 57.15,155.07 | ISP1.4 57.15,152.84 57.15,153.16
N$9  (via drill 0.8 pad 1.93)
  Bottom 0.406: IO2.24 41.91,153.01 41.91,150.94 45.4,147.45 129.22,147.45 SW7.1
  Bottom 0.61: SW7.1 v134.62,138.56 SW7.2
N$10  (via drill 0.8 pad 1.93)
  Bottom 0.406: IO2.25 39.05,152.96 39.05,150.94 43.5,146.5 110.49,146.5 SW6.1
  Bottom 0.61: SW6.1 v114.94,138.56 SW6.2
N$11  (via drill 0.8 pad 1.93)
  Bottom 0.406: IO2.26 38.1,153.14 38.1,150.31 42.86,145.54 91.12,145.54 SW5.1
  Bottom 0.61: SW5.1 v94.61,138.56 SW5.2
N$12  (via drill 0.8 pad 1.93)
  Bottom 0.406: IO2.27 37.15,153.32 37.15,149.67 42.23,144.59 72.07,144.59 SW4.1
  Bottom 0.61: SW4.1 v74.61,138.56 SW4.2
N$13  (via drill 0.8 pad 1.93)
  Bottom 0.406: IO2.28 36.2,153.5 36.2,149.03 41.59,143.64 53.02,143.64 SW3.1
  Bottom 0.61: SW3.1 v54.61,138.56 SW3.2
N$14  (via drill 0.8 pad 1.93)
  Bottom 0.406: IO2.30 32.7,152.26 32.7,146.5 34.61,144.59 SW2.1
  Bottom 0.61: SW2.2 v34.61,138.56 SW2.1
N$15  (via drill 0.8 pad 1.93)
  Bottom 0.406: IO2.31 31.75,152.44 31.75,146.5 26.35,140.78 26.35,137.29 24.13,135.06 SW1.2 | SW1.1 14.61,139.19
  Bottom 0.61: SW1.2 v14.61,138.56 SW1.1
N$16
  Bottom 0.406: IO2.19 45.35,155.23 45.9,155.23 47.69,153.44 R23.1 R24.2
N$17
  Bottom 0.406: IO1.3 arc-90 21.91,160.61
  Bottom 0.61: 21.91,160.61 D18.A 21.91,163.96 23.18,165.23 C8.C+
  Bottom 1.676: D18.A 20.95,163
N$18
  Bottom 0.406: D17.A2 24.29,170.15 25.08,169.36 32.38,169.36 35.88,165.86 35.85,165.86 IO2.7
N$19  (via drill 0.6 pad 2.18)
  Top 0.406: v6.67,155.38 v7.94,155.38 v7.94,143.32 v6.67,143.32
N$20
  Bottom 0.406: R19.1 T2.3
N$21
  Bottom 0.406: T2.1 16.51,168.09 R20.1
N$22
  Bottom 0.61: D19.K D18.K | T1.2 TL1.1 6.67,169.04 | 6.67,169.04 6.67,163.96 7.62,163 | 6.67,169.04 R18.2
  Bottom 1.676: D18.K 17.14,163 | 7.62,163 D19.K
N$23
  Bottom 0.61: R19.2 R18.1 T1.1
N$24
  Bottom 0.406: 20.64,166.81 R20.2 | R22.2 20.64,166.81 | 20.64,166.81 28.57,166.81 34.29,161.1 34.95,161.1 IO2.2
N$26
  Bottom 0.406: IO2.14 45.57,161.74 53.34,161.74 63.18,151.89 133.35,151.89 141.92,160.47 R25.1
N$35  (via drill 0.6 pad 2.18)
  Bottom 0.61: T3.3 v145.73,165.86 REP1.-
N$36
  Bottom 0.406: R2.1 D2.A
N$37
  Bottom 0.406: R4.1 D4.A
N$39
  Bottom 0.406: R6.1 75.56,170.94 D6.A
N$40
  Bottom 0.406: R8.1 89.53,170.94 D8.A
N$41
  Bottom 0.406: R10.1 103.5,170.94 D10.A
N$42
  Bottom 0.406: R12.1 131.13,170.94 D12.A
N$43
  Bottom 0.406: R14.1 145.1,170.94 D14.A
N$44
  Bottom 0.406: R16.1 159.07,170.94 D16.A
N$46
  Bottom 0.406: R3.1 D3.A
N$47
  Bottom 0.406: R5.1 D5.A
N$48
  Bottom 0.406: R7.1 82.55,170.94 D7.A
N$49
  Bottom 0.406: IO4.7 72.39,167.13 72.71,167.45 84.77,167.45 86.84,169.51 D8.K
N$50
  Bottom 0.406: IO4.5 69.85,168.72 70.48,169.36 72.39,169.36 72.87,169.83 D6.K
N$51
  Bottom 0.406: IO4.6 71.12,168.09 71.44,168.4 78.74,168.4 79.85,169.51 D7.K
N$52
  Bottom 0.406: IO4.4 68.58,168.09 D5.K
N$54
  Bottom 0.406: IO4.2 66.04,166.81 64.45,168.4 53.02,168.4 51.75,169.67 D3.K
N$55
  Bottom 0.406: IO4.1 64.77,166.5 63.82,167.45 46.99,167.45 44.77,169.67 D2.K
N$56  (via drill 0.6 pad 1.68)
  Top 0.406: v62.87,164.75 v62.87,160.62
  Bottom 0.406: D1.K 37.78,169.99 41.27,166.5 61.28,166.5 v62.87,164.75 | v62.87,160.62 62.87,158.56 63.5,157.93 65.72,157.93 66.04,158.24 IO4.15
N$57
  Bottom 0.406: R9.1 96.52,170.94 D9.A
N$58  (via drill 0.6 pad 1.68)
  Top 0.406: v124.46,164.75 v124.46,160.62
  Bottom 0.406: IO5.15 127.64,158.24 127,157.61 125.09,157.61 124.46,158.24 v124.46,160.62 | v124.46,164.75 124.46,164.91 124.14,165.23 98.42,165.23 93.98,169.67 93.98,170.78 D9.K
N$59
  Bottom 0.406: IO5.1 126.36,166.18 126.05,166.5 104.14,166.5 100.97,169.67 100.97,170.78 D10.K
N$60
  Bottom 0.406: IO5.3 128.91,170.78 D12.K
N$61
  Bottom 0.406: IO5.2 127.64,167.13 127,167.77 109.86,167.77 107.95,169.67 107.95,170.78 D11.K | D11.K
N$62
  Bottom 0.406: R11.1 110.49,170.94 D11.A
N$63
  Bottom 0.406: R13.1 138.11,170.94 D13.A
N$64
  Bottom 0.406: D13.K 133.67,170.94 130.18,167.45 IO5.4
N$65
  Bottom 0.406: IO5.5 131.44,167.13 133.67,169.36 142.24,169.36 142.72,169.83 D14.K
N$66
  Bottom 0.406: R15.1 152.08,170.94 D15.A
N$67
  Bottom 0.406: IO5.6 132.72,167.13 133.99,168.4 143.19,168.4 144.15,169.36 149.07,169.36 149.7,169.99 D15.K
N$68
  Bottom 0.406: IO5.7 133.99,167.13 134.3,167.45 143.83,167.45 144.46,168.09 154.94,168.09 156.69,169.83 D16.K
N$69
  Bottom 0.406: IO1.1 21.91,155.88 21.91,155.07
  Bottom 0.61: 15.88,155.07 14.29,155.07 12.38,153.48 12.38,151.57 11.76,150.95 K1.5 | 15.88,155.07 21.59,155.07 | 21.59,155.07 21.91,155.07 24.13,155.07 C7.+ | 15.88,155.07 C6.+ | 21.59,155.07 R26.2 C3.1
N$70
  Bottom 0.61: D19.A 7.62,159.83 K2.1
N$71
  Bottom 0.406: T3.1 R25.2
STROBE
  Bottom 0.406: 70.17,155.7 73.34,155.7 75.88,153.16 131.13,153.16 131.76,153.8 131.76,157.93 131.44,158.24 IO5.12 | IO4.12 69.85,158.24 70.17,157.93 70.17,155.7 | 70.17,155.7 62.55,155.7 54.61,163.64 42.95,163.64 IO2.10
(copper drawn outside any net)
  shapes: Bottom circle x2

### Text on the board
Bottom: PaJa-trb
wago-cervena: Dobre | Zapni | Spatne | kola | zivoty | 0 | 1 | 2 | 3 | 4 | 5 | 6 | 7 | 8 | 9 | 10 | 1 | 2 | 3 | 4 | 5 | 1 | 2 | 3 | 4 | 5 | 6 | 7 | 8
